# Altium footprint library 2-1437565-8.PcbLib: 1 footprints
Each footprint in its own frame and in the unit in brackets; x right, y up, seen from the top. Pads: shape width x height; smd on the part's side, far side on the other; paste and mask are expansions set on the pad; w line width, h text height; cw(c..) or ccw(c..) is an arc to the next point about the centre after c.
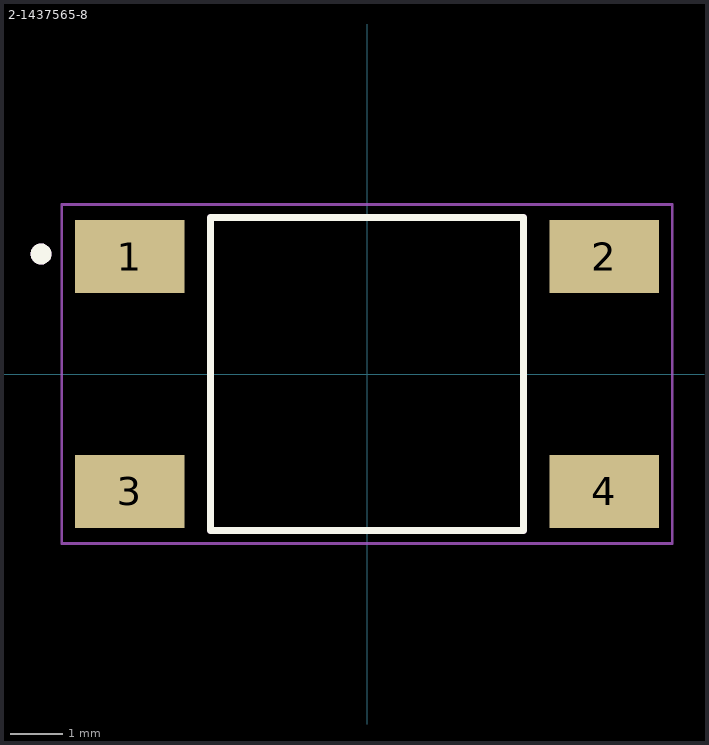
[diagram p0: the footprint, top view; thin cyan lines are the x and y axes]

## 2-1437565-8 [mm]
pads (4):
  rect 2.1x1.4 smd: 1(-4.55,2.25) 2(4.55,2.25) 3(-4.55,-2.25) 4(4.55,-2.25)
Top Overlay:
  circle w0.2: c-6.25,2.3 r0.1
  lines w0.127: -3,-3 3,-3 3,3 -3,3 -3,-3
Mechanical 13:
  circle w0.2: c-6.25,2.3 r0.1
  lines w0.127: -3,-3 -3,3 3,3 3,-3 -3,-3
Mechanical 15:
  lines w0.05: -5.85,-3.25 -5.85,3.25 5.85,3.25 5.85,-3.25 -5.85,-3.25
3D body "2-1437565-8.STEP": height 4.28, standoff -0.1, extent -4.953,-3 5.047,3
